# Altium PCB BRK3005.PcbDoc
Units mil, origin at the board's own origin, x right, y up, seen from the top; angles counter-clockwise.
Board outline 5039.37 x 3307.09 mil, 2 copper layers (Top Layer, Bottom Layer); 24 components, 124 nets, 375 pads, 72 vias.
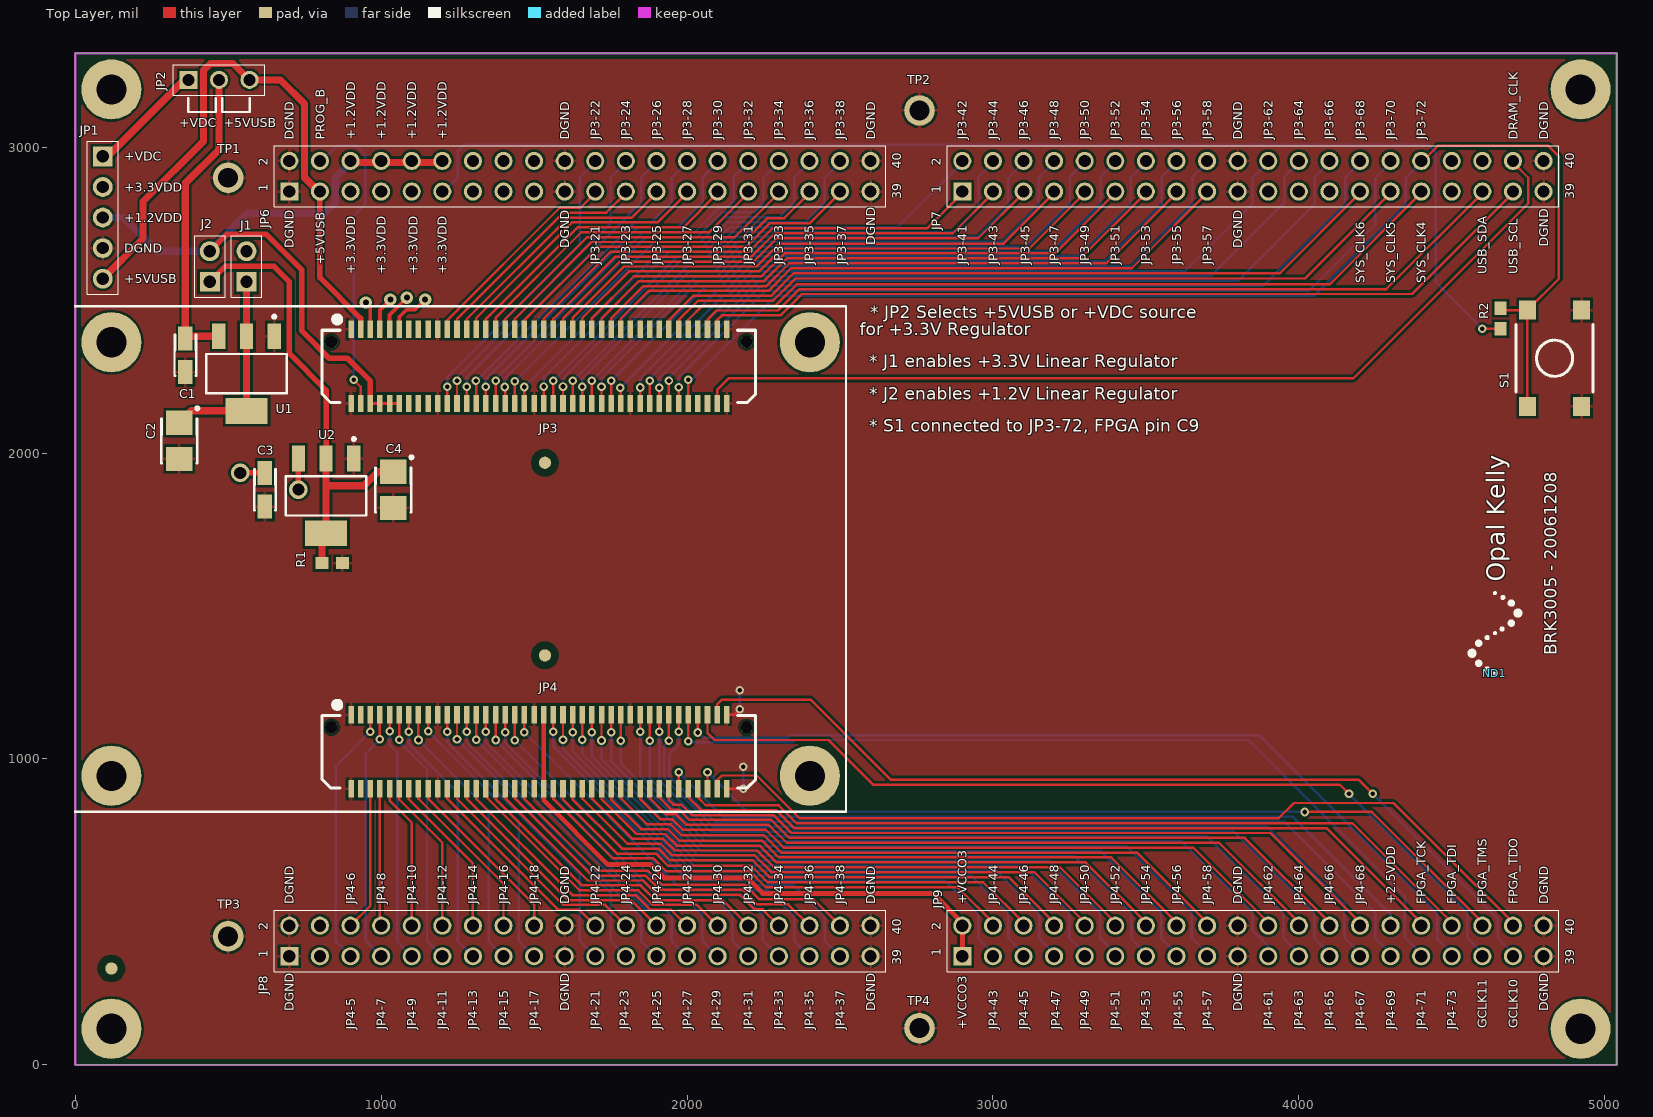
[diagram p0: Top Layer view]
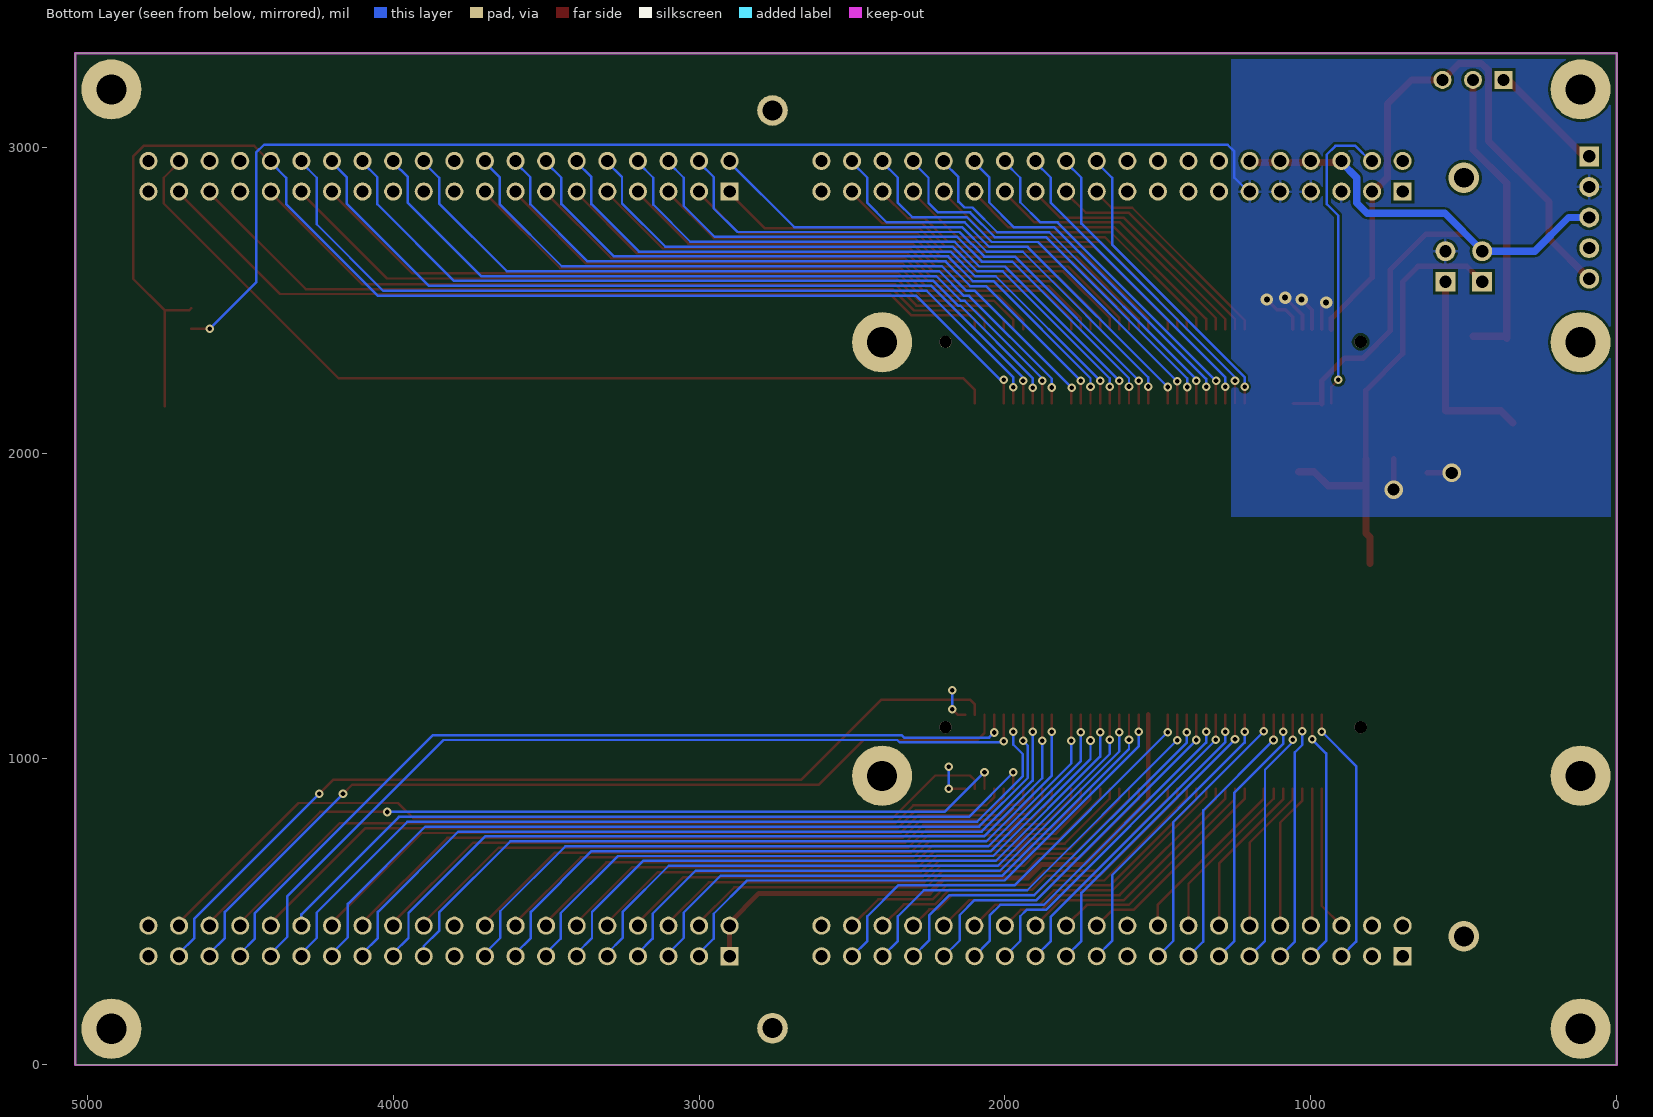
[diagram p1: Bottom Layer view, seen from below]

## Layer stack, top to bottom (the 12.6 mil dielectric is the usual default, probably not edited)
Top Layer: signal copper 1.4
Dielectric: dielectric 12.6, FR-4, Dk 4.8
Bottom Layer: signal copper 1.4

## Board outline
0,0 0,3307.09 5039.37,3307.09 5039.37,0

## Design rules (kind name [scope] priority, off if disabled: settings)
Clearance Fiducial [All vs ((Not PadIsPlated) And (HoleSize = 0))] p1: gap=25
Clearance [All] p2: gap=8
FabricationTestPointUsage TestPointUsage [All] p1: valid=0 allowmultiple=FALSE
FabricationTestpoint Testpoint [All] p1: side=3 testpointundercomponent=TRUE minsize=40 maxsize=100 preferedsize=60 minholesize=0 maxholesize=40 preferedholesize=32 testpointgrid=1 allowsidetop=TRUE allowsidebottom=TRUE usegrid=TRUE gridtolerance=0.01
HoleSize [All] p1: absolutevalues=TRUE maxlimit=236.22 minlimit=15 maxpercent=80.000 minpercent=20.000
PolygonConnect "Via Connect" [IsVia] p1: connectstyle=Direct reliefconductorwidth=10 reliefentries=4 polygonreliefangle="90 Angle"
PolygonConnect [All] p2: connectstyle=Relief reliefconductorwidth=10 reliefentries=4 polygonreliefangle="90 Angle"
RoutingVias [All] p1: holewidth=15 width=25 viastyle="Through Hole" minholewidth=15 minwidth=25 maxholewidth=50 maxwidth=100
SilkscreenOverComponentPads [All] p1: minsilkscreentomaskgap=10
SolderMaskExpansion [All] p1: expansion=4
Width [All] p1: maxlimit=40 minlimit=8 preferedwidth=8 minimp=50.000000 maximp=50.000000 favimp=50.000000
24 further rules are at their usual default settings.

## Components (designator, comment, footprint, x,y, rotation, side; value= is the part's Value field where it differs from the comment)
C1 "SM-A, 10v, 10%" TC3216-1206 360,2320 r270 top
C2 "SM-B, 10v, low-ESR" TC3528-1411 340,2040 r270 top
C3 "SM-A, 10v, 10%" TC3216-1206 620,1880 r270 top
C4 "SM-B, 10v, low-ESR" TC3528-1411 1040,1880 r270 top
J1 "0.1\" spacing" HDR1X2 560,2560 r90 top
J2 "0.1\" spacing" HDR1X2 440,2560 r90 top
JP1 "Header, 6-Pin, Single Row" HDR1X5 90,2970 r270 top
JP2 "*" HDR1X3 370,3220 r0 top
JP3 "BTE-040" BTE-040 1515.75,2283.47 r0 top locked
JP4 "BTE-040" BTE-040 1515.75,1023.62 r0 top locked
JP6 "Header 20X2" HDR2X20 700,2855 r0 top locked
JP7 "Header 20X2" HDR2X20 2900,2855 r0 top locked
JP8 "Header 20X2" HDR2X20 700,355 r0 top locked
JP9 "Header 20X2" HDR2X20 2900,355 r0 top locked
ND1 "OKLOGO" oklogotiny 4641.26,1280 r90 top
R1 "SM-0603, 5%, 1/10W" CR1608-0603 840,1640 r180 top
R2 "SM-0603, 5%, 1/10W" CR1608-0603 4660,2440 r270 top
S1 "SMD, tactile" SW_BFS 4836,2310 r270 top
TP1 "TESTPOINT" TP_MED#1 500,2900 r90 top
TP2 "TESTPOINT" TP_MED#1 2760,3120 r0 top
TP3 "TESTPOINT" TP_MED#2 540,420 r90 top
TP4 "TESTPOINT" TP_MED#1 2760,120 r90 top
U1 "3.3v 800mA" DSO-G3 560,2260 r180 top
U2 "1.2v 1A" DSO-G3 820,1860 r180 top

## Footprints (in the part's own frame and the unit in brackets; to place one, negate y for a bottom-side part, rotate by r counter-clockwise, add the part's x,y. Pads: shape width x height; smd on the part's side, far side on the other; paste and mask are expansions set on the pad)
BTE-040 [mm] "0.8mm Samtech socket"
  rect 0.46x1.45 smd: 1(-15.6,3.085) 2(-15.6,-3.085) 3(-14.8,3.085) 4(-14.8,-3.085) 5(-14,3.085) 6(-14,-3.085) 7(-13.2,3.085) 8(-13.2,-3.085) 9(-12.4,3.085) 10(-12.4,-3.085) 11(-11.6,3.085) 12(-11.6,-3.085) 13(-10.8,3.085) 14(-10.8,-3.085) 15(-10,3.085) 16(-10,-3.085) 17(-9.2,3.085) 18(-9.2,-3.085) 19(-8.4,3.085) 20(-8.4,-3.085) 21(-7.6,3.085) 22(-7.6,-3.085) 23(-6.8,3.085) 24(-6.8,-3.085) 25(-6,3.085) 26(-6,-3.085) 27(-5.2,3.085) 28(-5.2,-3.085) 29(-4.4,3.085) 30(-4.4,-3.085) 31(-3.6,3.085) 32(-3.6,-3.085) 33(-2.8,3.085) 34(-2.8,-3.085) 35(-2,3.085) 36(-2,-3.085) 37(-1.2,3.085) 38(-1.2,-3.085) 39(-0.4,3.085) 40(-0.4,-3.085) 41(0.4,3.085) 42(0.4,-3.085) 43(1.2,3.085) 44(1.2,-3.085) 45(2,3.085) 46(2,-3.085) 47(2.8,3.085) 48(2.8,-3.085) 49(3.6,3.085) 50(3.6,-3.085) 51(4.4,3.085) 52(4.4,-3.085) 53(5.2,3.085) 54(5.2,-3.085) 55(6,3.085) 56(6,-3.085) 57(6.8,3.085) 58(6.8,-3.085) 59(7.6,3.085) 60(7.6,-3.085) 61(8.4,3.085) 62(8.4,-3.085) 63(9.2,3.085) 64(9.2,-3.085) 65(10,3.085) 66(10,-3.085) 67(10.8,3.085) 68(10.8,-3.085) 69(11.6,3.085) 70(11.6,-3.085) 71(12.4,3.085) 72(12.4,-3.085) 73(13.2,3.085) 74(13.2,-3.085) 75(14,3.085) 76(14,-3.085) 77(14.8,3.085) 78(14.8,-3.085) 79(15.6,3.085) 80(15.6,-3.085)
  round 1.02 hole 1.02: 81(-17.235,2.035) 82(17.235,2.035)
  silkscreen extent -18,-3 18,4.15
CR1608-0603 [mm] "Chip Resistor; Body 1.6 x 0.8 mm (LxW typ)"
  rect 1.1x1 smd: 1(-0.85,0) 2(0.85,0)
DSO-G3 [mm] "SOT-223/SC-73; 4 Leads; Body 6.7 x 7.3 mm, inc. leads (LxW max)"
  rect 1.1x2.15 smd: 1(-2.3,-3.1) 2(0,-3.1) 3(2.3,-3.1)
  rect 3.5x2.15 smd: 4(0,3.1)
  silkscreen extent -3.35,-4.85 3.35,1.63
HDR1X2 [mil] ".1\" 1x2 Header"
  rect 65x65 hole 40: 1(0,0)
  round 65 hole 40: 2(100,0)
  silkscreen extent -50,-50 150,50
HDR1X3 [mm] "Connector; Header; 3 Position"
  rect 1.5x1.5 hole 1.016: 1(0,0)
  round 1.5 hole 1.016: 2(2.54,0) 3(5.08,0)
  silkscreen extent -1.27,-1.27 6.35,1.27
HDR1X5 [mil] ".1\" 1x5 Header"
  rect 65x65 hole 40: 1(0,0)
  round 65 hole 40: 2(100,0) 3(200,0) 4(300,0) 5(400,0)
  silkscreen extent -50,-50 450,50
HDR2X20 [mm]
  rect 1.5x1.5 hole 1.016: 1(0,0)
  round 1.5 hole 1.016: 2(0,2.54) 3(2.54,0) 4(2.54,2.54) 5(5.08,0) 6(5.08,2.54) 7(7.62,0) 8(7.62,2.54) 9(10.16,0) 10(10.16,2.54) 11(12.7,0) 12(12.7,2.54) 13(15.24,0) 14(15.24,2.54) 15(17.78,0) 16(17.78,2.54) 17(20.32,0) 18(20.32,2.54) 19(22.86,0) 20(22.86,2.54) 21(25.4,0) 22(25.4,2.54) 23(27.94,0) 24(27.94,2.54) 25(30.48,0) 26(30.48,2.54) 27(33.02,0) 28(33.02,2.54) 29(35.56,0) 30(35.56,2.54) 31(38.1,0) 32(38.1,2.54) 33(40.64,0) 34(40.64,2.54) 35(43.18,0) 36(43.18,2.54) 37(45.72,0) 38(45.72,2.54) 39(48.26,0) 40(48.26,2.54)
  silkscreen extent -1.27,-1.27 49.53,3.81
oklogotiny [mil] "Opal Kelly silkscreen logo (50 mil)."
  silkscreen extent -3,-82 266,82
SW_BFS [mm] "Omron BFS tactile switch (SMD)"
  rect 1.6x1.4 smd: 1(-4,-2.25) 1(4,-2.25) 2(-4,2.25) 2(4,2.25)
  silkscreen extent -2.8,-3.2 2.8,3.2, body extent -4,-3.15 4,3.15, height 3.1
TC3216-1206 [mm] "Capacitor, SM Tantalum; Body 3.2 x 1.6 mm (LxW typ)"
  rect 2x1.2 smd: 1(-1.4,0) 2(1.4,0)
  silkscreen extent -1.7,-0.9 1.7,0.9
TC3528-1411 [mm] "Capacitor, SM Tantalum; Body 3.5 x 2.8 mm (LxW typ)"
  rect 2x2.2 smd: 1(-1.5,0) 2(1.5,0)
  silkscreen extent -2.82,-1.5 1.85,1.63
TP_MED#1 [mil] "Testpoint - medium sized"
  round 100 hole 65: 1(0,0)
TP_MED#2 [mil] "Testpoint - medium sized"
  round 100 hole 65: 1(0,40)

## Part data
C1 C2 C3 C4: library part "Capacitor Pol", "Tantalum capacitor"
J1 J2: library part "Jumper 1X2", "Header"
JP1: library part "Header 1X5"
JP2: library part "Header 1X3", "Header, 3-Pin, Single Row"
JP3 JP4: library part BTE/BSE-040, "Header/Socket - 80-pin - 0.80mm"
JP6 JP7 JP8 JP9: "Header, 20-Pin, Dual row"
ND1: "Opal Kelly PCB Logo"
R1 R2: library part Resistor, "Thick-film resistor"
S1: library part SW-PB, "Pushbutton"
TP1 TP2 TP3 TP4: "Testpoint"
U1: library part LM1117, "LDO regulator"
U2: library part FAN1112, "LDO regulator"

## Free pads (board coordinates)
  round 196.85 hole 98.43: 0(118.11,118.11) 0(118.11,944.88) 0(118.11,2362.2) 0(118.11,3188.98) 0(2401.57,944.88) 0(2401.57,2362.2) 0(4921.26,118.11) 0(4921.26,3188.98)
  round 40 smd mask+20: FD0(118.11,314.96) FD0(1535.43,1338.58) FD0(1535.43,1968.5)

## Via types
v1: diameter 28, hole 15, Top Layer to Bottom Layer, tented both sides, 66 vias
v2: diameter 40, hole 20, Top Layer to Bottom Layer, tented both sides, 4 vias
v3: diameter 60, hole 40, Top Layer to Bottom Layer, tented both sides, 2 vias

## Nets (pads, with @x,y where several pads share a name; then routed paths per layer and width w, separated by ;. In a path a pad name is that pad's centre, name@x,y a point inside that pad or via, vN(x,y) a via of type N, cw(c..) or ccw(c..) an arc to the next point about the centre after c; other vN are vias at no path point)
+1.2VDD: J2.2 JP1.3 JP3.6 JP3.8 JP3.10 JP3.12 JP6.6 JP6.8 JP6.10 JP6.12 | length 2356
  Top Layer w10: JP3.6 JP3.8 JP3.10 JP3.12
  Top Layer w18: J2.2 495,2715 625,2715 740,2600 740,2400 830,2310 890,2310 964.57,2235.43 JP3.6
  Top Layer w23: JP6.6@900,2950 1000,2950 1100,2950 JP6.12@1200,2950
  Bottom Layer w23: J2.2 440,2662 562,2784 816,2784 850,2818 850,2900 JP6.6@900,2950
  Bottom Layer w24: JP1.3 158,2770 268,2660 J2.2
+2.5VDD: JP4.70 JP9.30 | length 2601.2
  Top Layer w8: JP4.70 v1(1972.44,956.44)
  Bottom Layer w8: v1(1972.44,956.44) 2118.16,810.72 3981.28,810.72 4300,492 JP9.30@4300,465
+3.3VDD: C3.1 J1.2 JP1.2 JP3.5 JP3.7 JP3.9 JP3.11 JP6.5 JP6.7 JP6.9 JP6.11 R2.2 U2.3 | length 4735.5
  Top Layer w8: v1(4600,2406) 4600.54,2406.54 R2.2
  Top Layer w12: v2(950,2492) 964.57,2477.43 JP3.5 ; JP3.7 996.06,2468.06 v2(1030,2502) ; JP3.9 1027.56,2451.56 v2(1084,2508) ; JP3.11 1059.06,2445.06 1082,2468 1110,2468 v2(1144,2502)
  Top Layer w18: v3(539.12,1935.12) C3.1 ; v3(729.45,1880.55) U2.3
  Bottom Layer w8: JP6.11@1200,2850 1202.5,2852.5 1250,2900 1250,2986 1272,3008 4422,3008 4448,2982 4448,2558 v1(4600,2406)
+5VUSB: JP1.5 JP2.3 JP3.3 JP6.3 | length 2024.8
  Top Layer w18: JP6.3@800,2850 800,2573.5 933.07,2440.43 JP3.3
  Top Layer w23: JP1.5 222,2702 222,2822 420,3020 420,3252 442,3274 516,3274 JP2.3 671,3220 750.13,3140.87 750.13,2899.87 797.5,2852.5 JP6.3@800,2850
+VCCO3: JP4.41 JP4.42 JP9.1 JP9.2 | length 1924.6
  Top Layer w16: JP4.41 JP4.42 1531.5,864.5 1741.28,654.72 1880.95,654.72 1924.55,611.12 2196.88,611.12 2247.28,560.72 2804.28,560.72 2900,465 JP9.2 JP9.1
+VDC: JP1.1 JP2.1 | length 383.6
  Top Layer w24: JP1.1 106.5,2970 356.5,3220 JP2.1
B_BUS0: JP3.21 JP6.21 | length 685.2
  Top Layer w8: JP3.21 1216.54,2434.54 1584,2802 1652,2802 JP6.21@1700,2850
B_BUS1: JP3.22 JP6.22 | length 988.2
  Top Layer w8: JP3.22 v1(1216.54,2216.54)
  Bottom Layer w8: v1(1216.54,2216.54) 1216.54,2248.54 1650,2682 1650,2900 JP6.22@1700,2950
B_BUS2: JP3.23 JP6.23 | length 755.7
  Top Layer w8: JP3.23 1248.03,2438.03 1596,2786 1736,2786 JP6.23@1800,2850
B_BUS3: JP3.24 JP6.24 | length 1016.7
  Top Layer w8: JP3.24 v1@1248.03,2235.97
  Bottom Layer w8: v1(1248,2236) 1248,2248 1750,2750 1750,2900 JP6.24@1800,2950
B_BUS4: JP4.11 JP8.11 | length 848.5
  Top Layer w8: v1(1059.06,1063.06) JP4.11
  Bottom Layer w8: v1(1059.06,1063.06) 1059.06,1055.8 1150,964.85 1150,405 JP8.11
B_BUS5: JP4.10 JP8.10 | length 477.2
  Top Layer w8: JP4.10 1027.56,864.44 1100,792 JP8.10
B_BUS6: JP4.9 JP8.9 | length 820.1
  Top Layer w8: v1(1027.56,1090.44) JP4.9
  Bottom Layer w8: v1(1027.56,1090.44) 1027.56,1046.44 1052,1022 1052,403 JP8.9
B_BUS7: JP4.8 JP8.8 | length 448.8
  Top Layer w8: JP4.8 996.06,458.94 JP8.8
B_BUS8: JP4.7 JP8.7 | length 829.9
  Top Layer w8: v1(996.06,1064.06) JP4.7
  Bottom Layer w8: v1(996.06,1064.06) 950,1018 950,405 JP8.7
B_BUS9: JP4.6 JP8.6 | length 473.9
  Top Layer w8: JP8.6 964.57,519.57 JP4.6
B_BUS10: JP4.5 JP8.5 | length 856.6
  Top Layer w8: v1(964.57,1089.43) JP4.5
  Bottom Layer w8: JP8.5 852,403 852,976.87 v1(964.57,1089.43)
DGND: C1.2 C2.2 C3.2 C4.2 JP1.4 JP3.1 JP3.2 JP3.19 JP3.20 JP3.39 JP3.40 JP3.59 JP3.60 JP3.79 JP3.80 JP4.1 JP4.2 JP4.19 JP4.20 JP4.39 JP4.40 JP4.59 JP4.60 JP4.79 JP4.80 JP6.1 JP6.2 JP6.19 JP6.20 JP6.39 JP6.40 JP7.19 JP7.20 JP7.39 JP7.40 JP8.1 JP8.2 JP8.19 JP8.20 JP8.39 JP8.40 JP9.19 JP9.20 JP9.39 JP9.40 R1.1 S1.2 TP1.1 TP2.1 TP3.1 TP4.1 U1.1 U2.1 | length 244.7
  Top Layer w8: JP4.80 v1(2183.83,902.17) ; JP4.79 2155.08,1145.08 v1(2172,1162)
  Bottom Layer w8: v1(2172,1162) v1(2172,1224) ; v1(2183.83,902.17) v1(2183.83,974.17) v1@2183.83,981.83
DRAM_CLK: JP3.78 JP7.38 | length 3103.2
  Top Layer w8: JP3.78 2098.43,2206.43 2136,2244 4178,2244 4750,2816 4750,2900 JP7.38@4700,2950
FPGA_TCK: JP4.72 JP9.32 | length 2593.6
  Top Layer w8: JP4.72 2003.94,874.06 2045.28,832.72 2291.28,832.72 2350,774 4091,774 JP9.32@4400,465
FPGA_TDI: JP4.74 JP9.34 | length 2661.8
  Top Layer w8: JP4.74 2035.43,874.57 2061.28,848.72 2299.28,848.72 2358,790 4175,790 JP9.34@4500,465
FPGA_TDO: JP4.78 JP9.38 | length 2876.9
  Top Layer w8: JP4.78 2098.43,930.43 2114,946 2228,946 2368,806 3934,806 3984,856 4309,856 JP9.38@4700,465
FPGA_TMS: JP4.76 JP9.36 | length 2791.8
  Top Layer w8: JP4.76 v1(2066.93,957.07) ; v1(4018.72,826.72) 4238.28,826.72 JP9.36@4600,465
  Bottom Layer w8: v1(2066.93,957.07) 2197.28,826.72 v1(4018.72,826.72)
GCLK10: JP4.77 JP9.37 | length 3021.7
  Top Layer w8: JP4.77 2098.43,1178.43 2114,1194 2404,1194 2665.31,932.69 4195.31,932.69 v1(4242,886)
  Bottom Layer w8: v1(4242,886) 4650,478 4650,415 JP9.37@4700,365
GCLK11: JP4.75 JP9.35 | length 2941.1
  Top Layer w8: JP4.75 2066.93,1085.07 2090,1062 2462,1062 2608,916 4134,916 v1(4164,886)
  Bottom Layer w8: v1(4164,886) 4550,500 4550,415 JP9.35@4600,365
J_1.2: C4.1 J2.1 R1.2 U2.2 U2.4 | length 1515.8
  Top Layer w18: J2.1 490,2610 650,2610 700,2560 700,2325 820,2205 U2.2
  Top Layer w24: R1.2 806.54,1724.49 U2.4 U2.2 ; 820,1893 943.5,1893 989.56,1939.06 C4.1
J_3.3: C2.1 J1.1 U1.2 U1.4 | length 658.2
  Top Layer w24: C2.1 378.9,2137.95 U1.4 U1.2 J1.1
J_VIN: C1.1 JP2.2 U1.3 | length 1002.8
  Top Layer w24: U1.3 366.93,2382.05 C1.1 360,2882 470,2992 JP2.2
L_BUS0: JP4.68 JP9.28 | length 2461.9
  Top Layer w8: JP4.68 1940.94,865.06 1955.28,850.72 1981.28,850.72 2015.28,816.72 2283.28,816.72 2342,758 3907,758 JP9.28@4200,465
L_BUS1: JP4.65 JP9.25 | length 2689.8
  Top Layer w8: v1(1909.45,1088.55) JP4.65
  Bottom Layer w8: v1(1909.45,1088.55) 1909.45,929.4 2076.13,762.72 3787.28,762.72 4050,500 4050,415 JP9.25@4100,365
L_BUS2: JP4.66 JP9.26 | length 2388.5
  Top Layer w8: JP4.66 1909.45,873.4 1948.13,834.72 1973.28,834.72 2007.28,800.72 2275.28,800.72 2334,742 3823,742 JP9.26@4100,465
L_BUS3: JP4.63 JP9.23 | length 2614.3
  Top Layer w8: v1(1877.95,1060.05) JP4.63
  Bottom Layer w8: v1(1877.95,1060.05) 1877.95,937.34 2068.57,746.72 3699.28,746.72 3950,496 3950,415 JP9.23@4000,365
L_BUS4: JP4.64 JP9.24 | length 2320.8
  Top Layer w8: JP4.64 1877.95,872.05 1931.28,818.72 1964.13,818.72 1998.13,784.72 2267.28,784.72 2326,726 3739,726 JP9.24@4000,465
L_BUS5: JP4.61 JP9.21 | length 2542.2
  Top Layer w8: v1(1846.46,1089.54) JP4.61
  Bottom Layer w8: v1(1846.46,1089.54) 1846.46,945.54 2061.28,730.72 3617.28,730.72 3850,498 3850,438 3900,388 JP9.21@3900,365
L_BUS6: JP4.62 JP9.22 | length 2253.7
  Top Layer w8: JP4.62 1846.46,869.54 1913.28,802.72 1952.9,802.72 1987.12,768.5 2257.5,768.5 2316,710 3655,710 JP9.22@3900,465
L_BUS7: JP4.57 JP9.17 | length 2384.2
  Top Layer w8: v1(1783.46,1059.46) JP4.57
  Bottom Layer w8: v1(1783.46,1059.46) 1783.46,985.39 2054.13,714.72 3437.28,714.72 3650,502 3650,415 JP9.17@3700,365
L_BUS8: JP4.58 JP9.18 | length 2115
  Top Layer w8: JP4.58 1783.46,872.54 1869.28,786.72 1946.13,786.72 1982.13,750.72 2251.28,750.72 2308,694 3471,694 JP9.18@3700,465
L_BUS9: JP4.55 JP9.15 | length 2310.1
  Top Layer w8: v1(1751.97,1087.97) JP4.55
  Bottom Layer w8: v1(1751.97,1087.97) 1751.97,992.88 2046.13,698.72 3351.28,698.72 3550,500 3550,415 JP9.15@3600,365
L_BUS10: JP4.56 JP9.16 | length 2049.1
  Top Layer w8: JP4.56 1751.97,868.03 1849.28,770.72 1937.09,770.72 1974.5,733.31 2244.69,733.31 2300,678 3387,678 JP9.16@3600,465
L_BUS11: JP4.53 JP9.13 | length 2236
  Top Layer w8: v1(1720.47,1060.47) JP4.53
  Bottom Layer w8: v1(1720.47,1060.47) 1720.47,1000.38 2038.13,682.72 3265.28,682.72 3452,496 3452,413 JP9.13@3500,365
L_BUS12: JP4.54 JP9.14 | length 1979.7
  Top Layer w8: JP4.54 1720.47,869.53 1835.28,754.72 1928.9,754.72 1966.87,716.75 2237.25,716.75 2292,662 3303,662 JP9.14@3500,465
L_BUS13: JP4.51 JP9.11 | length 2164.3
  Top Layer w8: v1(1688.98,1086.98) JP4.51
  Bottom Layer w8: v1(1688.98,1086.98) 1688.98,1007.87 2030.13,666.72 3183.28,666.72 3350,500 3350,415 JP9.11@3400,365
L_BUS14: JP4.52 JP9.12 | length 1910.3
  Top Layer w8: JP4.52 1688.98,871.02 1821.28,738.72 1922.13,738.72 1960.13,700.72 2229.28,700.72 2284,646 3219,646 JP9.12@3400,465
L_BUS15: JP4.49 JP9.9 | length 2090.9
  Top Layer w8: v1(1657.48,1062.52) JP4.49
  Bottom Layer w8: v1(1657.48,1062.52) 1657.48,1016.25 2023.01,650.72 3099.28,650.72 3250,500 3250,415 JP9.9@3300,365
L_BUS16: JP4.50 JP9.10 | length 1842.1
  Top Layer w8: JP4.50 1657.48,870.52 1805.28,722.72 1914.13,722.72 1952.13,684.72 2221.28,684.72 2276,630 3135,630 JP9.10@3300,465
L_BUS17: JP4.47 JP9.7 | length 2014.9
  Top Layer w8: v1(1625.98,1087.98) JP4.47
  Bottom Layer w8: v1(1625.98,1087.98) 1625.98,1025.07 2016.33,634.72 3011.28,634.72 3152,494 3152,413 JP9.7@3200,365
L_BUS18: JP4.48 JP9.8 | length 1775.1
  Top Layer w8: JP4.48 1625.98,868.02 1787.28,706.72 1906.13,706.72 1944.13,668.72 2214.63,668.72 2269.35,614 3051,614 JP9.8@3200,465
L_BUS19: JP4.45 JP9.5 | length 1943.3
  Top Layer w8: v1(1594.49,1062.49) JP4.45
  Bottom Layer w8: v1(1594.49,1062.49) 1594.49,1032.36 2008.13,618.72 2929.28,618.72 3050,498 3050,415 JP9.5@3100,365
L_BUS20: JP4.46 JP9.6 | length 1714
  Top Layer w8: JP4.46 1594.49,867.51 1771.28,690.72 1898.13,690.72 1938.13,650.72 2210,650.72 2264,596.72 2968.28,596.72 JP9.6@3105,460
L_BUS21: JP4.44 JP9.4 | length 1644.6
  Top Layer w8: JP4.44 1562.99,869.01 1757.28,674.72 1890.13,674.72 1932.13,632.72 2205.28,632.72 2257.28,580.72 2884.28,580.72 JP9.4@3005,460
L_BUS22: JP4.43 JP9.3 | length 1868.5
  Top Layer w8: v1(1562.99,1089.01) JP4.43
  Bottom Layer w8: v1(1562.99,1089.01) 1562.99,1041.01 2001.28,602.72 2843.28,602.72 2952,494 2952,413 JP9.3@3000,365
L_BUS23: JP4.38 JP8.38 | length 1235.9
  Top Layer w8: JP4.38 1468.5,869.5 1703.28,634.72 1872.13,634.72 1918.13,588.72 2189.28,588.72 2237.28,540.72 2414.28,540.72 JP8.38
L_BUS24: JP4.37 JP8.37 | length 1439.9
  Top Layer w8: v1(1468.5,1087.5) JP4.37
  Bottom Layer w8: v1(1468.5,1087.5) 1969.28,586.72 2349.28,586.72 2450,486 2450,405 JP8.37
L_BUS25: JP4.36 JP8.36 | length 1166.5
  Top Layer w8: JP4.36 1437.01,870.99 1689.28,618.72 1864.13,618.72 1910.13,572.72 2181.28,572.72 2229.28,524.72 2330.28,524.72 JP8.36
L_BUS26: JP4.35 JP8.35 | length 1386.9
  Top Layer w8: v1(1437.01,1061.01) JP4.35
  Bottom Layer w8: v1(1437.01,1061.01) 1927.29,570.72 2265.28,570.72 2350,486 2350,405 JP8.35
L_BUS27: JP4.34 JP8.34 | length 1097.1
  Top Layer w8: JP4.34 1405.51,872.49 1675.28,602.72 1856.13,602.72 1902.13,556.72 2171.28,556.72 2220,508 2247,508 JP8.34
L_BUS28: JP4.33 JP8.33 | length 1322.9
  Top Layer w8: v1(1405.51,1087.51) JP4.33
  Bottom Layer w8: v1(1405.51,1087.51) 1405.51,1053.34 1904.13,554.72 2181.28,554.72 2248,488 2248,407 JP8.33
L_BUS29: JP4.32 JP8.32 | length 1030.7
  Top Layer w8: JP4.32 1374.02,868.83 1656.13,586.72 1848.13,586.72 1896.13,538.72 2116.28,538.72 JP8.32
L_BUS30: JP4.31 JP8.31 | length 1250.5
  Top Layer w8: v1(1374.02,1062.02) JP4.31
  Bottom Layer w8: v1(1374.02,1062.02) 1897.31,538.72 2099.28,538.72 2148,490 2148,407 JP8.31
L_BUS31: JP4.30 JP8.30 | length 957.8
  Top Layer w8: JP4.30 1342.52,876.33 1648.13,570.72 1840.13,570.72 1888.13,522.72 2032.28,522.72 JP8.30
L_BUS32: JP4.29 JP8.29 | length 1187
  Top Layer w8: v1(1342.52,1088.52) JP4.29
  Bottom Layer w8: v1(1342.52,1088.52) 1342.52,1053.48 1873.28,522.72 2015.28,522.72 2050,488 2050,405 JP8.29
L_BUS33: JP4.28 JP8.28 | length 893.6
  Top Layer w8: JP4.28 1311.02,868.98 1625.28,554.72 1832.13,554.72 1880.13,506.72 1948.28,506.72 JP8.28
L_BUS34: JP4.27 JP8.27 | length 1112.5
  Top Layer w8: v1(1311.02,1062.98) JP4.27
  Bottom Layer w8: v1(1311.02,1062.98) 1311.02,1061.83 1866.13,506.72 1929.28,506.72 1950,486 1950,405 JP8.27
L_BUS35: JP4.26 JP8.26 | length 824.3
  Top Layer w8: JP4.26 1279.53,870.47 1611.28,538.72 1816.28,538.72 JP8.26
L_BUS36: JP4.25 JP8.25 | length 1047.1
  Top Layer w8: v1(1279.53,1088.47) JP4.25
  Bottom Layer w8: v1(1279.53,1088.47) 1279.53,1055.32 1850,484.85 1850,405 JP8.25
L_BUS37: JP4.24 JP8.24 | length 756.1
  Top Layer w8: JP4.24 1248.03,869.97 1595.28,522.72 1732.28,522.72 JP8.24
L_BUS38: JP4.23 JP8.23 | length 1018.7
  Top Layer w8: v1(1248.03,1063.97) JP4.23
  Bottom Layer w8: v1(1248.03,1063.97) 1750,562 1750,405 JP8.23
L_BUS39: JP4.22 JP8.22 | length 687.8
  Top Layer w8: JP4.22 1216.54,869.46 1579.28,506.72 1648.28,506.72 JP8.22
L_BUS40: JP4.21 JP8.21 | length 990.3
  Top Layer w8: v1(1216.54,1088.54) JP4.21
  Bottom Layer w8: v1(1216.54,1088.54) 1216.54,1053.46 1650,620 1650,405 JP8.21
L_BUS41: JP4.18 JP8.18 | length 590.7
  Top Layer w8: JP4.18 1153.54,870.46 1500,524 JP8.18
L_BUS42: JP4.17 JP8.17 | length 933.6
  Top Layer w8: v1(1153.54,1090.46) JP4.17
  Bottom Layer w8: v1(1153.54,1090.46) 1450,794 1450,405 JP8.17
L_BUS43: JP4.16 JP8.16 | length 562.3
  Top Layer w8: JP4.16 1122.05,869.95 1400,592 JP8.16
L_BUS44: JP4.15 JP8.15 | length 905.2
  Top Layer w8: v1(1122.05,1062.05) JP4.15
  Bottom Layer w8: v1(1122.05,1062.05) 1352,832.09 1352,403 JP8.15
L_BUS45: JP4.14 JP8.14 | length 533.9
  Top Layer w8: JP4.14 1090.55,867.45 1300,658 JP8.14
L_BUS46: JP4.13 JP8.13 | length 876.8
  Top Layer w8: v1(1090.55,1089.45) JP4.13
  Bottom Layer w8: v1(1090.55,1089.45) 1090.55,1049.45 1250,890 1250,405 JP8.13
L_BUS47: JP4.12 JP8.12 | length 505.5
  Top Layer w8: JP4.12 1059.06,866.94 1200,726 JP8.12
PROG_B: JP3.4 JP6.4 | length 1020.8
  Top Layer w8: v1(910.5,2239.5) 933.07,2216.93 JP3.4
  Bottom Layer w8: JP6.4@800,2950 802.5,2952.5 854,3004 920,3004 948,2976 948,2814 910.5,2776.5 v1(910.5,2239.5)
R_BUS0: JP3.25 JP6.25 | length 823.9
  Top Layer w8: JP3.25 1279.53,2437.53 1612,2770 1820,2770 JP6.25@1900,2850
R_BUS1: JP3.26 JP6.26 | length 1045
  Top Layer w8: JP3.26 v1(1279.53,2216.47)
  Bottom Layer w8: v1(1279.53,2216.47) 1279.53,2247.53 1850,2818 1850,2900 JP6.26@1900,2950
R_BUS2: JP3.27 JP6.27 | length 894.5
  Top Layer w8: JP3.27 1311.02,2441.02 1624,2754 1904,2754 JP6.27@2000,2850
R_BUS3: JP3.28 JP6.28 | length 1107
  Top Layer w8: v1(1310,2236) 1311.02,2234.98 JP3.28
  Bottom Layer w8: v1(1310,2236) 1828,2754 1884,2754 1950,2820 1950,2900 JP6.28@2000,2950
R_BUS4: JP3.29 JP6.29 | length 961.5
  Top Layer w8: JP3.29 1342.52,2438.52 1642,2738 1988,2738 JP6.29@2100,2850
R_BUS5: JP3.30 JP6.30 | length 1179.1
  Top Layer w8: JP3.30 v1(1342.52,2217.48)
  Bottom Layer w8: v1(1342.52,2217.48) 1342.52,2242.52 1838,2738 1970,2738 2052,2820 2052,2902 JP6.30@2100,2950
R_BUS6: JP3.31 JP6.31 | length 1032.1
  Top Layer w8: JP3.31 1374.02,2442.02 1654,2722 2072,2722 JP6.31@2200,2850
R_BUS7: JP3.32 JP6.32 | length 1245.3
  Top Layer w8: JP3.32 v1(1374.02,2236.02)
  Bottom Layer w8: v1(1374.02,2236.02) 1374.02,2240.61 1855.4,2722 2025.4,2722 2106.13,2802.72 2132.72,2802.72 2152,2822 2152,2902 JP6.32@2200,2950
R_BUS8: JP3.33 JP6.33 | length 1097.9
  Top Layer w8: JP3.33 1405.51,2437.51 1674,2706 2156,2706 JP6.33@2300,2850
R_BUS9: JP3.34 JP6.34 | length 1319.1
  Top Layer w8: v1(1404,2216) 1405.51,2214.49 JP3.34
  Bottom Layer w8: v1(1404,2216) 1404,2244 1866,2706 2033.4,2706 2114.13,2786.72 2218.72,2786.72 2250,2818 2250,2900 JP6.34@2300,2950
R_BUS10: JP3.35 JP6.35 | length 1167.3
  Top Layer w8: JP3.35 1437.01,2439.01 1688,2690 2185.4,2690 2263.4,2768 2318,2768 JP6.35@2400,2850
R_BUS11: JP3.36 JP6.36 | length 1380.2
  Top Layer w8: JP3.36 v1(1437.01,2234.99)
  Bottom Layer w8: v1(1437.01,2234.99) 1892.02,2690 2043.4,2690 2124.13,2770.72 2302.72,2770.72 2350,2818 2350,2900 JP6.36@2400,2950
R_BUS12: JP3.37 JP6.37 | length 1233.2
  Top Layer w8: JP3.37 1468.5,2434.5 1708,2674 2193.4,2674 2270.13,2750.72 2400.72,2750.72 JP6.37@2500,2850
R_BUS13: JP3.38 JP6.38 | length 1438.3
  Top Layer w8: v1(1468,2216) 1468.5,2215.5 JP3.38
  Bottom Layer w8: v1(1468,2216) 1926,2674 2051.4,2674 2132.13,2754.72 2386.72,2754.72 2450,2818 2450,2900 JP6.38@2500,2950
R_BUS14: JP3.41 JP7.1 | length 1573.1
  Top Layer w8: JP3.41 1531.5,2439.5 1750,2658 2202,2658 2278.72,2734.72 2784.72,2734.72 JP7.1@2900,2850
R_BUS15: JP3.42 JP7.2 | length 1745
  Top Layer w8: JP3.42 v1(1531.5,2217.5)
  Bottom Layer w8: v1(1531.5,2217.5) 1531.5,2247.5 1942,2658 2059.4,2658 2140.13,2738.72 2688.72,2738.72 JP7.2@2900,2950
R_BUS16: JP3.43 JP7.3 | length 1641.3
  Top Layer w8: JP3.43 1562.99,2438.99 1766,2642 2210.17,2642 2286.89,2718.72 2868.72,2718.72 JP7.3@3000,2850
R_BUS17: JP3.44 JP7.4 | length 1868.3
  Top Layer w8: v1(1562,2236.61) 1562.99,2235.62 JP3.44
  Bottom Layer w8: v1(1562,2236.61) 1967.39,2642 2067.4,2642 2148.13,2722.72 2874.72,2722.72 2952,2800 2952,2902 JP7.4@3000,2950
R_BUS18: JP3.45 JP7.5 | length 1710.7
  Top Layer w8: JP3.45 1594.49,2440.49 1780,2626 2218,2626 2294.16,2702.16 2952.16,2702.16 JP7.5@3100,2850
R_BUS19: JP3.46 JP7.6 | length 1934.1
  Top Layer w8: JP3.46 v1(1594.49,2217.51)
  Bottom Layer w8: v1(1594.49,2217.51) 1594.49,2244.49 1976,2626 2075.4,2626 2156.13,2706.72 2948.72,2706.72 3050,2808 3050,2900 JP7.6@3100,2950
R_BUS20: JP3.47 JP7.7 | length 1780.1
  Top Layer w8: JP3.47 1625.98,2441.98 1794,2610 2227.4,2610 2302.13,2684.72 3034.72,2684.72 JP7.7@3200,2850
R_BUS21: JP3.48 JP7.8 | length 1995.3
  Top Layer w8: JP3.48 v1(1626,2236)
  Bottom Layer w8: v1(1626,2236) 2000,2610 2084,2610 2164.72,2690.72 3028.72,2690.72 3150,2812 3150,2900 JP7.8@3200,2950
R_BUS22: JP3.49 JP7.9 | length 1848.3
  Top Layer w8: JP3.49 1657.48,2441.48 1810,2594 2235.4,2594 2310.13,2668.72 3118.72,2668.72 JP7.9@3300,2850
R_BUS23: JP3.50 JP7.10 | length 2067.4
  Top Layer w8: JP3.50 v1(1657.48,2216.52)
  Bottom Layer w8: v1(1657.48,2216.52) 1657.48,2244.08 2007.4,2594 2090.71,2594 2171.44,2674.72 3110.72,2674.72 3252,2816 3252,2902 JP7.10@3300,2950
R_BUS24: JP3.51 JP7.11 | length 1916.5
  Top Layer w8: JP3.51 1688.98,2440.98 1826,2578 2243.4,2578 2318.13,2652.72 3202.72,2652.72 JP7.11@3400,2850
R_BUS25: JP3.52 JP7.12 | length 2133.7
  Top Layer w8: v1(1688,2236) 1688.98,2235.02 JP3.52
  Bottom Layer w8: v1(1688,2236) 2030,2578 2097.4,2578 2178.13,2658.72 3196.72,2658.72 3352,2814 3352,2902 JP7.12@3400,2950
R_BUS26: JP3.53 JP7.13 | length 1984.7
  Top Layer w8: JP3.53 1720.47,2440.47 1842,2562 2252,2562 2326.72,2636.72 3286.72,2636.72 JP7.13@3500,2850
R_BUS27: JP3.54 JP7.14 | length 2204.6
  Top Layer w8: JP3.54 v1(1720.47,2216.47)
  Bottom Layer w8: v1(1720.47,2216.47) 1720.47,2244.47 2038,2562 2105.4,2562 2186.13,2642.72 3278.72,2642.72 3450,2814 3450,2900 JP7.14@3500,2950
R_BUS28: JP3.55 JP7.15 | length 2052.9
  Top Layer w8: JP3.55 1751.97,2439.97 1858,2546 2259.4,2546 2334.13,2620.72 3370.72,2620.72 JP7.15@3600,2850
R_BUS29: JP3.56 JP7.16 | length 2269.3
  Top Layer w8: JP3.56 v1(1751.97,2236.03)
  Bottom Layer w8: v1(1751.97,2236.03) 2061.94,2546 2113.4,2546 2194.13,2626.72 3364.72,2626.72 3552,2814 3552,2902 JP7.16@3600,2950
R_BUS30: JP3.57 JP7.17 | length 2121.1
  Top Layer w8: JP3.57 1783.46,2439.46 1874,2530 2266.08,2530 2340.08,2604 3454,2604 JP7.17@3700,2850
R_BUS31: JP3.58 JP7.18 | length 2327
  Top Layer w8: v1(1782,2214) 1783.46,2212.54 JP3.58
  Bottom Layer w8: v1(1782,2214) 2098,2530 2125.4,2530 2206.13,2610.72 3448.72,2610.72 3652,2814 3652,2902 JP7.18@3700,2950
SYS_CLK4: JP3.71 JP7.31 | length 2598.6
  Top Layer w8: JP3.71 2003.94,2435.94 2050,2482 2289.4,2482 2359.4,2552 4102,2552 JP7.31@4400,2850
SYS_CLK5: JP3.69 JP7.29 | length 2529.2
  Top Layer w8: JP3.69 1972.44,2434.44 2036,2498 2281.4,2498 2354.13,2570.72 4020.72,2570.72 JP7.29@4300,2850
SYS_CLK6: JP3.67 JP7.27 | length 2461
  Top Layer w8: JP3.67 1940.94,2434.94 2020,2514 2274,2514 2348,2588 3938,2588 JP7.27@4200,2850
T_BUS0: JP3.62 JP7.22 | length 2476.6
  Top Layer w8: JP3.62 v1(1846.46,2214.46)
  Bottom Layer w8: v1(1846.46,2214.46) 1846.46,2243.06 2117.4,2514 2134,2514 2214.72,2594.72 3628.72,2594.72 3850,2816 3850,2900 JP7.22@3900,2950
T_BUS1: JP3.64 JP7.24 | length 2545.7
  Top Layer w8: JP3.64 v1(1877.95,2235.95)
  Bottom Layer w8: v1(1877.95,2235.95) 1877.95,2243.95 2132,2498 2144,2498 2224.72,2578.72 3712.72,2578.72 3952,2818 3952,2902 JP7.24@4000,2950
T_BUS2: JP3.66 JP7.26 | length 2617.4
  Top Layer w8: JP3.66 v1(1909.45,2213.45)
  Bottom Layer w8: v1(1909.45,2213.45) 1909.45,2245.45 2146.14,2482.14 2153.52,2482.14 2234.1,2562.72 3800.72,2562.72 4052,2814 4052,2902 JP7.26@4100,2950
T_BUS3: JP3.68 JP7.28 | length 2685.6
  Top Layer w8: JP3.68 v1(1940.94,2236.94)
  Bottom Layer w8: v1(1940.94,2236.94) 1940.94,2246.94 2240.72,2546.72 3882.72,2546.72 4152,2816 4152,2902 JP7.28@4200,2950
T_BUS4: JP3.70 JP7.30 | length 2792.8
  Top Layer w8: JP3.70 v1(1972.44,2215.68)
  Bottom Layer w8: v1(1972.44,2215.68) 1972.44,2247.04 2256.13,2530.72 4032.72,2530.72 4250,2748 4250,2900 JP7.30@4300,2950
T_BUS5: JP3.72 JP7.32 R2.1 S1.1 | length 4254.8
  Top Layer w8: JP3.72 v1(2003.94,2239.94) ; JP7.32@4400,2950 4402.5,2952.5 4454,3004 4816,3004 4850,2970 4850,2570.06 S1.1@4747.42,2467.48 ; R2.1 4665.98,2467.48 S1.1@4747.42,2467.48 ; S1.1@4747.42,2152.52 S1.1@4747.42,2467.48
  Bottom Layer w8: v1(2003.94,2239.94) 2015.94,2239.94 2290.72,2514.72 4050.72,2514.72 4350,2814 4350,2900 JP7.32@4400,2950
T_BUS6: JP4.67 JP9.27 | length 2789.3
  Top Layer w8: v1(1940.94,1059.06) JP4.67
  Bottom Layer w8: v1(1940.94,1059.06) 1925.45,1043.56 1925.45,937.84 2084.56,778.72 3895.28,778.72 4148,526 4148,417 JP9.27@4200,365
T_BUS7: JP4.69 JP9.29 | length 2860.6
  Top Layer w8: v1(1972.44,1088.44) JP4.69
  Bottom Layer w8: v1(1972.44,1088.44) 1972.44,1046.44 1941.45,1015.45 1941.45,944.55 2091.28,794.72 3953.28,794.72 4250,498 4250,415 JP9.29@4300,365
T_BUS8: JP4.71 JP9.31 | length 2854.7
  Top Layer w8: v1(2003.94,1058.06) JP4.71
  Bottom Layer w8: v1(2003.94,1058.06) 2008,1054 2344,1054 2352,1062 3836,1062 4346,552 4346,419 JP9.31@4400,365
T_BUS9: JP4.73 JP9.33 | length 2877.2
  Top Layer w8: v1(2035.43,1086.57) JP4.73
  Bottom Layer w8: v1(2035.43,1086.57) 2052,1070 2330,1070 2338,1078 3870,1078 4452,496 4452,413 JP9.33@4500,365
USB_SCL: JP3.77 JP7.37 | length 2803.2
  Top Layer w8: JP3.77 2098.43,2434.43 2114,2450 2306,2450 2376,2520 4370,2520 JP7.37@4700,2850
USB_SDA: JP3.75 JP7.35 | length 2736.2
  Top Layer w8: JP3.75 2066.93,2436.93 2096,2466 2297.4,2466 2367.4,2536 4286,2536 JP7.35@4600,2850
pads on no net: JP3.13 JP3.14 JP3.15 JP3.16 JP3.17 JP3.18 JP3.61 JP3.63 JP3.65 JP3.73 JP3.74 JP3.76 JP3.81 JP3.82 JP4.3 JP4.4 JP4.81 JP4.82 JP6.13 JP6.14 JP6.15 JP6.16 JP6.17 JP6.18 JP7.21 JP7.23 JP7.25 JP7.33 JP7.34 JP7.36 JP8.3 JP8.4

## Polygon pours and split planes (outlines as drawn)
DGND on Top Layer "DGND_Poly" (solid, remove dead copper, pour order 1000): 19.68,19.68 5019.69,19.68 5019.69,3287.4 19.68,3287.4
+3.3VDD on Bottom Layer "33VDD_Poly" (solid, remove dead copper, pour order 1000): 19.68,1791.34 1259.84,1791.34 1259.84,3287.4 19.68,3287.4

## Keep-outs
Keep-Out Layer:
  the board outline again, w7.01

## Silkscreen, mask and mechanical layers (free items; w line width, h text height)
Top Overlay:
  lines w7.99: 0,826.77 2519.69,826.77 2519.69,2480.32 0,2480.32
  lines w8: 370,3160 370,3115 460,3115 460,3160 ; 480,3160 480,3115 570,3115 570,3160
  text "+VDC" at 340,3065 h30
  text "+5VUSB" at 485,3065 h30
  text "DGND" at 715,3025 h30 r90
  text "PROG_B" at 815,3025 h30 r90
  text "+1.2VDD" at 915,3025 h30 r90
  text "+1.2VDD" at 1015,3025 h30 r90
  text "+1.2VDD" at 1115,3025 h30 r90
  text "+1.2VDD" at 1215,3025 h30 r90
  text "DGND" at 1615,3025 h30 r90
  text "JP3-22" at 1715,3025 h30 r90
  text "JP3-24" at 1815,3025 h30 r90
  text "JP3-26" at 1915,3025 h30 r90
  text "JP3-28" at 2015,3025 h30 r90
  text "JP3-30" at 2115,3025 h30 r90
  text "JP3-32" at 2215,3025 h30 r90
  text "JP3-34" at 2315,3025 h30 r90
  text "JP3-36" at 2415,3025 h30 r90
  text "JP3-38" at 2515,3025 h30 r90
  text "DGND" at 2615,3025 h30 r90
  text "JP3-42" at 2915,3025 h30 r90
  text "JP3-44" at 3015,3025 h30 r90
  text "JP3-46" at 3115,3025 h30 r90
  text "JP3-48" at 3215,3025 h30 r90
  text "JP3-50" at 3315,3025 h30 r90
  text "JP3-52" at 3415,3025 h30 r90
  text "JP3-54" at 3515,3025 h30 r90
  text "JP3-56" at 3615,3025 h30 r90
  text "JP3-58" at 3715,3025 h30 r90
  text "DGND" at 3815,3025 h30 r90
  text "JP3-62" at 3915,3025 h30 r90
  text "JP3-64" at 4015,3025 h30 r90
  text "JP3-66" at 4115,3025 h30 r90
  text "JP3-68" at 4215,3025 h30 r90
  text "JP3-70" at 4315,3025 h30 r90
  text "JP3-72" at 4415,3025 h30 r90
  text "DRAM_CLK" at 4715,3025 h30 r90
  text "DGND" at 4815,3025 h30 r90
  text "+VDC" at 160,2955 h30
  text "+3.3VDD" at 160,2855 h30
  text "+1.2VDD" at 160,2755 h30
  text "DGND" at 2615,2679.72 h30 r90
  text "DGND" at 4815,2675 h30 r90
  text "DGND" at 715,2670 h30 r90
  text "DGND" at 1615,2670 h30 r90
  text "DGND" at 3815,2670 h30 r90
  text "DGND" at 160,2655 h30
  text "+5VUSB" at 815,2615 h30 r90
  text "JP3-21" at 1715,2615 h30 r90
  text "JP3-23" at 1815,2615 h30 r90
  text "JP3-25" at 1915,2615 h30 r90
  text "JP3-27" at 2015,2615 h30 r90
  text "JP3-29" at 2115,2615 h30 r90
  text "JP3-31" at 2215,2615 h30 r90
  text "JP3-33" at 2315,2615 h30 r90
  text "JP3-35" at 2415,2615 h30 r90
  text "JP3-37" at 2520,2615 h30 r90
  text "JP3-41" at 2915,2615 h30 r90
  text "JP3-43" at 3015,2615 h30 r90
  text "JP3-45" at 3120,2615 h30 r90
  text "JP3-47" at 3215,2615 h30 r90
  text "JP3-49" at 3315,2615 h30 r90
  text "JP3-51" at 3415,2615 h30 r90
  text "JP3-53" at 3515,2615 h30 r90
  text "JP3-55" at 3615,2615 h30 r90
  text "JP3-57" at 3715,2615 h30 r90
  text "+3.3VDD" at 915,2585 h30 r90
  text "+3.3VDD" at 1015,2585 h30 r90
  text "+3.3VDD" at 1120,2585 h30 r90
  text "+3.3VDD" at 1215,2585 h30 r90
  text "USB_SDA" at 4615,2585 h30 r90
  text "USB_SCL" at 4715,2585 h30 r90
  text "+5VUSB" at 160,2555 h30
  text "SYS_CLK6" at 4215,2555 h30 r90
  text "SYS_CLK5" at 4315,2555 h30 r90
  text "SYS_CLK4" at 4415,2555 h30 r90
  text "* JP2 Selects +5VUSB or +VDC source" at 2598.43,2440.94 h40
  text "for +3.3V Regulator" at 2565,2385 h40
  text "* J1 enables +3.3V Linear Regulator" at 2595,2280 h40
  text "* J2 enables +1.2V Linear Regulator" at 2595,2175 h40
  text "* S1 connected to JP3-72, FPGA pin C9" at 2595,2070 h40
  text "BRK3005 - 20061208" at 4842.52,1338.58 h40 r90
  text "DGND" at 715,525 h30 r90
  text "JP4-6" at 915,525 h30 r90
  text "JP4-8" at 1015,525 h30 r90
  text "JP4-10" at 1115,525 h30 r90
  text "JP4-12" at 1215,525 h30 r90
  text "JP4-14" at 1315,525 h30 r90
  text "JP4-16" at 1415,525 h30 r90
  text "JP4-18" at 1515,525 h30 r90
  text "DGND" at 1615,525 h30 r90
  text "JP4-22" at 1715,525 h30 r90
  text "JP4-24" at 1815,525 h30 r90
  text "JP4-26" at 1915,525 h30 r90
  text "JP4-28" at 2015,525 h30 r90
  text "JP4-30" at 2115,525 h30 r90
  text "JP4-32" at 2215,525 h30 r90
  text "JP4-34" at 2315,525 h30 r90
  text "JP4-36" at 2415,525 h30 r90
  text "JP4-38" at 2515,525 h30 r90
  text "DGND" at 2615,525 h30 r90
  text "+VCCO3" at 2915,525 h30 r90
  text "JP4-44" at 3015,525 h30 r90
  text "JP4-46" at 3115,525 h30 r90
  text "JP4-48" at 3215,525 h30 r90
  text "JP4-50" at 3315,525 h30 r90
  text "JP4-52" at 3415,525 h30 r90
  text "JP4-54" at 3515,525 h30 r90
  text "JP4-56" at 3615,525 h30 r90
  text "JP4-58" at 3715,525 h30 r90
  text "DGND" at 3815,525 h30 r90
  text "JP4-62" at 3915,525 h30 r90
  text "JP4-64" at 4015,525 h30 r90
  text "JP4-66" at 4115,525 h30 r90
  text "JP4-68" at 4215,525 h30 r90
  text "+2.5VDD" at 4315,525 h30 r90
  text "FPGA_TCK" at 4415,525 h30 r90
  text "FPGA_TDI" at 4515,525 h30 r90
  text "FPGA_TMS" at 4615,525 h30 r90
  text "FPGA_TDO" at 4715,525 h30 r90
  text "DGND" at 4815,525 h30 r90
  text "DGND" at 715,175 h30 r90
  text "DGND" at 1615,175 h30 r90
  text "DGND" at 2615,175 h30 r90
  text "DGND" at 3815,175 h30 r90
  text "DGND" at 4815,175 h30 r90
  text "GCLK11" at 4615,120 h30 r90
  text "GCLK10" at 4715,120 h30 r90
  text "JP4-5" at 915,115 h30 r90
  text "JP4-7" at 1015,115 h30 r90
  text "JP4-9" at 1115,115 h30 r90
  text "JP4-11" at 1215,115 h30 r90
  text "JP4-13" at 1315,115 h30 r90
  text "JP4-15" at 1415,115 h30 r90
  text "JP4-17" at 1515,115 h30 r90
  text "JP4-21" at 1715,115 h30 r90
  text "JP4-23" at 1810,115 h30 r90
  text "JP4-25" at 1915,115 h30 r90
  text "JP4-27" at 2015,115 h30 r90
  text "JP4-29" at 2110,115 h30 r90
  text "JP4-31" at 2215,115 h30 r90
  text "JP4-33" at 2315,115 h30 r90
  text "JP4-35" at 2415,115 h30 r90
  text "JP4-37" at 2515,115 h30 r90
  text "+VCCO3" at 2915,115 h30 r90
  text "JP4-43" at 3015,115 h30 r90
  text "JP4-45" at 3115,115 h30 r90
  text "JP4-47" at 3220,115 h30 r90
  text "JP4-49" at 3315,115 h30 r90
  text "JP4-51" at 3415,115 h30 r90
  text "JP4-53" at 3515,115 h30 r90
  text "JP4-55" at 3620,115 h30 r90
  text "JP4-57" at 3715,115 h30 r90
  text "JP4-61" at 3915,115 h30 r90
  text "JP4-63" at 4015,115 h30 r90
  text "JP4-65" at 4115,115 h30 r90
  text "JP4-67" at 4215,115 h30 r90
  text "JP4-69" at 4315,115 h30 r90
  text "JP4-71" at 4415,115 h30 r90
  text "JP4-73" at 4515,115 h30 r90
Mechanical 2:
  the board outline again, w8

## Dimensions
0,0 to 0,3307.09 on Mechanical 1
0,0 to 5039.37,0 on Mechanical 1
